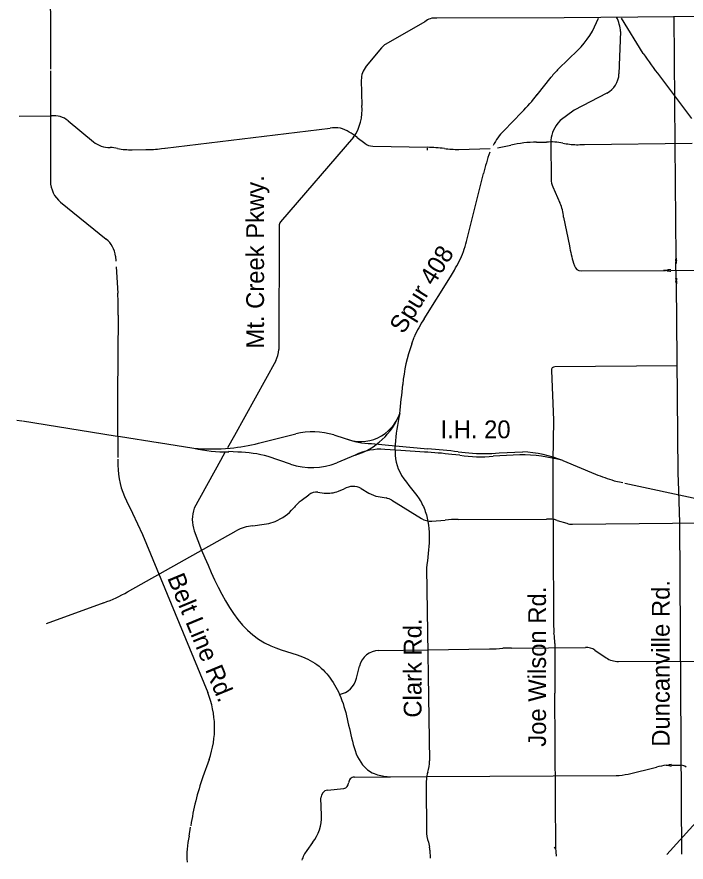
# Model space of a CAD drawing. Extents: x 105094 to 105814, y -291615 to -291123.
# Drawn here: x 105349.7 to 105395.2, y -291559 to -291501.5 of the extents above; entities that cross this region are included whole.
import ezdxf

# ---------------------------------------------------------------- set-up
doc = ezdxf.new("R2010")
doc.units = 0
doc.layers.add('G_MAP', color=7, linetype='Continuous')

msp = doc.modelspace()

# ---------------------------------------------------------------- linework, layer by layer
at = {"layer": 'G_MAP'}
for p, q in [((105377.412, -291501.861), (105374.763, -291503.381)), ((105386.9, -291501.593), (105378.226, -291501.612)), ((105392.278, -291504.008), (105390.808, -291501.606)), ((105390.741, -291502.528), (105390.632, -291505.402)), ((105374.469, -291503.628), (105373.428, -291504.888)), ((105386.523, -291505.058), (105387.831, -291503.79)), ((105351.948, -291505.204), (105351.945, -291512.686)), ((105373.098, -291505.826), (105373.13, -291507.561)), ((105385.069, -291506.818), (105386.012, -291505.62)), ((105393.398, -291505.54), (105395.562, -291508.449)), ((105382.789, -291509.27), (105384.026, -291508.006)), ((105349.809, -291508.273), (105352.01, -291508.268)), ((105353.144, -291508.593), (105354.871, -291510.016)), ((105359.738, -291510.458), (105370.969, -291509.092)), ((105372.571, -291509.718), (105367.603, -291515.468)), ((105372.822, -291509.726), (105373.327, -291510.122)), ((105359.492, -291510.49), (105359.734, -291510.458)), ((105373.879, -291510.318), (105377.592, -291510.399)), ((105377.606, -291510.594), (105377.606, -291510.468)), ((105379.723, -291510.538), (105381.875, -291510.49)), ((105385.026, -291510.052), (105385.693, -291510.048)), ((105385.993, -291510.106), (105386.013, -291512.581)), ((105386.817, -291510.116), (105387.033, -291510.154)), ((105387.979, -291510.219), (105388.128, -291510.206)), ((105388.124, -291510.206), (105388.289, -291510.206)), ((105388.283, -291510.206), (105395.62, -291510.118)), ((105357.506, -291510.564), (105358.436, -291510.548)), ((105380.445, -291516.09), (105381.407, -291512.173)), ((105386.125, -291513.096), (105386.616, -291514.188)), ((105352.637, -291514.134), (105355.742, -291516.646)), ((105386.865, -291515.16), (105387.266, -291517.107)), ((105367.502, -291515.758), (105367.482, -291524.152)), ((105356.361, -291517.805), (105356.392, -291518.147)), ((105356.405, -291518.532), (105356.528, -291520.33)), ((105387.534, -291518.277), (105387.599, -291518.471)), ((105394.522, -291519.316), (105394.512, -291518.293)), ((105379.176, -291519.207), (105379.431, -291518.761)), ((105388.05, -291518.796), (105393.673, -291518.78)), ((105394.157, -291518.774), (105403.813, -291518.671)), ((105377.367, -291522.065), (105379.176, -291519.207)), ((105376.528, -291523.767), (105376.692, -291523.305)), ((105367.272, -291524.927), (105364.469, -291530.009)), ((105394.596, -291525.268), (105386.261, -291525.339)), ((105349.659, -291528.962), (105349.985, -291529.014)), ((105350.037, -291529.011), (105356.347, -291530.032)), ((105356.35, -291530.032), (105356.705, -291530.077)), ((105356.512, -291529.638), (105356.521, -291530.464)), ((105364.466, -291530.009), (105364.001, -291530.855)), ((105366.108, -291530.537), (105368.635, -291529.9)), ((105371.227, -291529.969), (105372.003, -291530.209)), ((105356.521, -291530.464), (105356.537, -291531.501)), ((105356.705, -291530.077), (105359.279, -291530.487)), ((105359.289, -291530.487), (105361.695, -291530.871)), ((105373.792, -291530.561), (105375.414, -291530.716)), ((105363.839, -291531.126), (105363.516, -291531.714)), ((105364.685, -291531.13), (105364.059, -291531.104)), ((105375.788, -291531.023), (105374.697, -291530.949)), ((105375.414, -291530.716), (105377.616, -291530.917)), ((105377.393, -291531.136), (105375.788, -291531.023)), ((105379.699, -291531.114), (105380.416, -291531.178)), ((105382.489, -291531.194), (105384.08, -291531.127)), ((105356.537, -291531.611), (105356.537, -291532.018)), ((105363.516, -291531.714), (105361.734, -291534.95)), ((105368.285, -291531.954), (105366.768, -291531.44)), ((105372.678, -291531.34), (105371.422, -291531.855)), ((105379.812, -291531.34), (105379.26, -291531.298)), ((105383.881, -291531.323), (105382.076, -291531.414)), ((105386.142, -291531.721), (105386.142, -291535.712)), ((105386.804, -291531.714), (105389.032, -291532.635)), ((105390.308, -291533.08), (105390.896, -291533.206)), ((105391.025, -291533.239), (105395.988, -291534.311)), ((105369.01, -291534.436), (105369.515, -291534.041)), ((105370.146, -291533.866), (105370.577, -291533.919)), ((105371.549, -291533.794), (105371.939, -291533.639)), ((105373.092, -291533.62), (105373.606, -291533.923)), ((105394.784, -291535.958), (105394.703, -291533.758)), ((105357.109, -291534.441), (105357.532, -291535.286)), ((105374.246, -291534.161), (105374.778, -291534.258)), ((105375.182, -291534.413), (105377.2, -291535.659)), ((105357.532, -291535.286), (105358.207, -291536.749)), ((105377.895, -291535.827), (105378.805, -291535.758)), ((105379.683, -291535.716), (105385.69, -291535.706)), ((105386.42, -291535.783), (105387.085, -291535.974)), ((105365.712, -291536.152), (105366.478, -291536.035)), ((105367.101, -291535.893), (105367.228, -291535.847)), ((105387.476, -291536.038), (105400.477, -291535.916)), ((105394.919, -291558.499), (105394.784, -291535.958)), ((105357.193, -291540.634), (105364.572, -291536.494)), ((105358.207, -291536.749), (105362.644, -291547.493)), ((105361.734, -291536.491), (105362.228, -291537.808)), ((105377.532, -291539.042), (105377.733, -291552.147)), ((105355.578, -291541.38), (105351.642, -291542.818)), ((105383.313, -291544.467), (105388.356, -291544.421)), ((105386.265, -291544.16), (105386.258, -291547.535)), ((105374.294, -291544.63), (105377.613, -291544.577)), ((105377.616, -291544.577), (105381.818, -291544.516)), ((105388.988, -291544.61), (105389.758, -291545.128)), ((105390.6, -291545.382), (105396.039, -291545.348)), ((105372.771, -291546.521), (105372.965, -291545.699)), ((105404.954, -291546.176), (105393.9, -291558.515)), ((105386.326, -291558.152), (105386.258, -291547.535)), ((105362.741, -291552.048), (105362.321, -291553.23)), ((105394.2, -291552.441), (105394.849, -291552.441)), ((105391.253, -291553.036), (105393.191, -291552.564)), ((105370.802, -291554.135), (105371.913, -291554.015)), ((105377.501, -291553.911), (105377.523, -291556.881)), ((105370.384, -291555.854), (105370.346, -291554.659)), ((105361.372, -291557.259), (105361.466, -291556.642)), ((105369.778, -291557.702), (105369.391, -291558.233)), ((105377.668, -291557.679), (105377.743, -291558.014)), ((105377.77, -291558.227), (105377.788, -291558.769))]:
    msp.add_line(p, q, dxfattribs=at)
for points in [[(105351.861, -291495.302), (105351.861, -291496.675), (105351.948, -291501.725), (105351.945, -291505.087)], [(105411.499, -291501.48), (105410.689, -291501.429), (105402.938, -291501.448), (105398.63, -291501.464), (105394.402, -291501.522), (105386.9, -291501.593)], [(105394.519, -291517.95), (105394.464, -291510.177), (105394.377, -291501.487)], [(105389.807, -291506.706), (105387.579, -291507.871), (105386.636, -291508.569), (105386.473, -291508.765)], [(105394.703, -291533.758), (105394.661, -291532.535), (105394.545, -291519.678)], [(105356.544, -291521.829), (105356.499, -291527.322), (105356.505, -291529.638)], [(105386.032, -291525.579), (105386.181, -291528.96), (105386.142, -291531.721)], [(105386.145, -291535.712), (105386.161, -291536.71), (105386.187, -291543.027)], [(105372.631, -291553.242), (105377.552, -291553.209), (105390.451, -291553.135)], [(105386.375, -291558.634), (105386.368, -291558.322)]]:
    msp.add_lwpolyline(points, dxfattribs=at)
for centre, radius, start, end in [((105378.1, -291502.654), 1.05, 83.07832, 130.9045), ((105383.88, -291499.715), 5.675, 314.11801, 340.47111), ((105388.128, -291502.716), 2.62, 4.11097, 26.44974), ((105375.296, -291504.312), 1.073, 119.82621, 140.44246), ((105408.327, -291493.444), 19.214, 213.35291, 219.0151), ((105374.538, -291505.805), 1.44, 140.43016, 180.83718), ((105395.028, -291513.294), 11.839, 135.92224, 139.59606), ((105389.095, -291505.343), 1.539, 297.59289, 357.79335), ((105373.484, -291497.694), 14.746, 315.63422, 321.77924), ((105369.956, -291507.89), 3.191, 325.04347, 5.91858), ((105352.203, -291509.735), 1.479, 50.52458, 97.51739), ((105388.07, -291510.093), 2.077, 140.25815, 180.37563), ((105371.319, -291512.266), 3.194, 83.6786, 96.28966), ((105370.265, -291512.997), 4.151, 51.98483, 70.16577), ((105385.641, -291512.059), 3.989, 135.63825, 153.57418), ((105355.972, -291508.689), 1.724, 230.31591, 271.07482), ((105356.034, -291511.962), 1.549, 72.18476, 91.10008), ((105357.416, -291505.239), 5.326, 260.1832, 270.96742), ((105358.631, -291504.464), 6.087, 268.16713, 278.13438), ((105373.899, -291509.391), 0.928, 231.98539, 268.74947), ((105377.343, -291522.282), 11.885, 83.18639, 88.79633), ((105379.593, -291504.476), 6.063, 262.03544, 271.23647), ((105379.161, -291493.069), 17.666, 280.45516, 283.48557), ((105385.081, -291518.425), 8.373, 90.37928, 102.42174), ((105386.02, -291513.967), 3.933, 78.31779, 94.77526), ((105387.801, -291505.868), 4.354, 259.84276, 272.34706), ((105395.618, -291515.666), 14.633, 160.31203, 166.19304), ((105353.8, -291512.689), 1.855, 179.92378, 231.18426), ((105387.286, -291512.574), 1.272, 180.31145, 204.21822), ((105384.23, -291515.316), 2.64, 3.39624, 25.30466), ((105367.921, -291515.741), 0.419, 139.3264, 182.23943), ((105364.501, -291512.341), 16.379, 341.65763, 346.76632), ((105354.68, -291517.958), 1.688, 5.20574, 51.02254), ((105395.435, -291515.85), 8.265, 188.75302, 197.07456), ((105370.246, -291513.503), 10.584, 330.20806, 337.83741), ((105393.821, -291517.937), 0.698, 344.72477, 358.91907), ((105395.217, -291517.964), 0.698, 178.91899, 193.11329), ((105388.049, -291518.322), 0.475, 198.40379, 270.15733), ((105395.168, -291518.305), 0.698, 164.72465, 178.91895), ((105393.857, -291518.28), 0.698, 358.91908, 13.11338), ((105393.654, -291517.393), 1.387, 270.76398, 280.82156), ((105393.691, -291520.167), 1.387, 80.70638, 90.76396), ((105394.175, -291520.118), 1.387, 90.76396, 100.82154), ((105394.139, -291517.43), 1.387, 260.70638, 270.76396), ((105395.259, -291519.27), 0.781, 183.57649, 196.99396), ((105393.765, -291519.727), 0.781, 3.57633, 16.9938), ((105395.324, -291519.629), 0.781, 170.15893, 183.5764), ((105393.785, -291519.362), 0.781, 350.15886, 3.57633), ((105337.08, -291521.289), 19.471, 358.41266, 2.82338), ((105385.087, -291527.07), 9.2, 147.04162, 155.84276), ((105365.788, -291524.11), 1.694, 331.15433, 358.56912), ((105387.305, -291527.6), 11.438, 160.42061, 174.63328), ((105386.263, -291525.571), 0.231, 90.50591, 182.01142), ((105271.117, -291516.683), 105.261, 353.54323, 354.63233), ((105373.059, -291527.613), 2.803, 247.86945, 341.11355), ((105371.336, -291526.856), 4.68, 286.66119, 339.1655), ((105369.808, -291534.549), 4.795, 72.78287, 104.16114), ((105363.142, -291518.781), 12.125, 274.87424, 284.15957), ((105373.868, -291525.456), 5.106, 248.58264, 269.15505), ((105362.876, -291516.198), 14.72, 265.39731, 275.04979), ((105363.848, -291521.651), 9.469, 256.85349, 271.3712), ((105364.459, -291539.806), 8.679, 74.56594, 88.50249), ((105374.412, -291534.887), 3.948, 85.86503, 116.04918), ((105376.295, -291554.7), 23.59, 82.77987, 87.33177), ((105371.846, -291603.034), 72.348, 83.76877, 85.42582), ((105381.527, -291521.656), 9.586, 263.34497, 275.76133), ((105383.753, -291539.255), 8.135, 67.976, 87.69871), ((105381.208, -291523.332), 8.129, 260.1119, 276.1295), ((105383.982, -291541.682), 10.36, 74.19168, 90.55772), ((105361.955, -291532.018), 5.418, 180.00123, 206.56487), ((105369.722, -291527.713), 4.478, 251.28067, 292.31459), ((105396.08, -291514.51), 19.446, 248.75088, 252.73292), ((105372.531, -291534.599), 1.128, 60.23057, 121.69505), ((105370.041, -291534.713), 0.854, 82.93188, 128.03689), ((105370.82, -291531.962), 1.972, 262.94073, 291.69679), ((105374.599, -291532.236), 1.957, 239.53172, 259.60676), ((105371.052, -291537.047), 3.315, 128.03304, 140.71232), ((105374.568, -291535.409), 1.17, 58.32599, 79.63022), ((105363.8, -291535.72), 2.205, 159.55868, 200.44248), ((105366.215, -291533.098), 2.929, 290.2222, 320.83891), ((105377.807, -291534.675), 1.156, 238.3315, 274.37451), ((105379.488, -291540.838), 5.126, 87.81574, 97.65696), ((105385.893, -291537.269), 1.576, 70.47694, 97.39919), ((105365.938, -291538.973), 2.83, 94.57479, 118.85279), ((105366.262, -291533.649), 2.396, 275.17665, 290.50929), ((105387.404, -291535.255), 0.787, 246.03924, 275.18886), ((105352.903, -291533.469), 8.351, 288.68369, 300.91076), ((105390.213, -291543.032), 4.026, 179.92056, 186.09243), ((105382.125, -291544.134), 4.14, 359.65234, 9.37779), ((105388.367, -291545.534), 1.113, 56.0818, 90.53546), ((105374.316, -291546.018), 1.388, 90.91105, 166.7133), ((105382.036, -291537.079), 7.44, 268.32099, 275.40106), ((105383.155, -291548.518), 4.054, 87.76468, 95.92897), ((105390.591, -291543.89), 1.492, 236.08017, 270.3494), ((105371.357, -291546.187), 1.453, 280.24864, 346.70064), ((105356.698, -291549.898), 6.414, 340.41921, 22.0186), ((105375.44, -291552.186), 2.294, 341.61045, 0.95346), ((105394.673, -291558.643), 6.258, 97.61006, 103.69538), ((105393.844, -291551.69), 0.751, 269.99989, 283.68543), ((105393.844, -291553.192), 0.751, 76.31441, 89.99995), ((105394.2, -291553.149), 0.751, 89.99995, 103.68549), ((105394.2, -291551.733), 0.751, 256.31429, 269.99983), ((105394.849, -291552.99), 0.549, 50.24302, 89.98348), ((105381.666, -291553.884), 4.166, 166.46703, 180.37795), ((105390.431, -291549.663), 3.472, 270.33326, 283.70228), ((105378.8, -291559.091), 17.491, 160.42129, 171.65331), ((105372.633, -291553.639), 0.397, 90.37658, 181.29125), ((105370.857, -291554.643), 0.511, 96.13751, 181.74463), ((105371.874, -291553.656), 0.362, 276.15649, 1.23944), ((105367.544, -291555.946), 2.842, 321.84585, 1.85106), ((105380.276, -291556.792), 2.755, 181.86148, 198.78804), ((105367.789, -291558.631), 6.562, 167.93279, 183.48055), ((105371.417, -291559.711), 2.508, 143.91377, 161.30374), ((105376.638, -291558.263), 1.133, 1.82995, 12.70409), ((105385.961, -291558.332), 0.407, 1.46609, 51.14746)]:
    msp.add_arc(centre, radius, start, end, dxfattribs=at)
for points in [[(105375.711, -291528.52), (105375.711, -291532.484), (105377.038, -291534.32), (105377.45, -291535.17), (105377.532, -291539.042)], [(105362.228, -291537.808), (105366.935, -291544.324), (105369.782, -291545.395), (105371.616, -291547.616), (105372.547, -291551.018), (105373.33, -291552.576), (105374.2, -291553.093), (105375.091, -291553.226)]]:
    msp.add_spline(points, degree=3, dxfattribs=at)

# ---------------------------------------------------------------- texts
for s, height, rotation, p in [('Mt. Creek Pkwy.', 1.21107, 90, (105366.477, -291524.091)), ('Spur 408', 1.2111, 58.00127, (105375.964, -291523.16)), ('Belt Line Rd.', 1.21107, 292.49907, (105359.871, -291539.689)), ('Duncanville Rd.', 1.21107, 90, (105394.08, -291551.18)), ('Joe Wilson Rd.', 1.21107, 90, (105385.664, -291551.18)), ('Clark Rd.', 1.2111, 90, (105377.197, -291549.203))]:
    msp.add_text(s, height=height, rotation=rotation, dxfattribs=at).set_placement(p)
msp.add_text('I.H. 20', height=1.2111, dxfattribs=at).set_placement((105378.485, -291530.193))

doc.saveas('drawing.dxf')
